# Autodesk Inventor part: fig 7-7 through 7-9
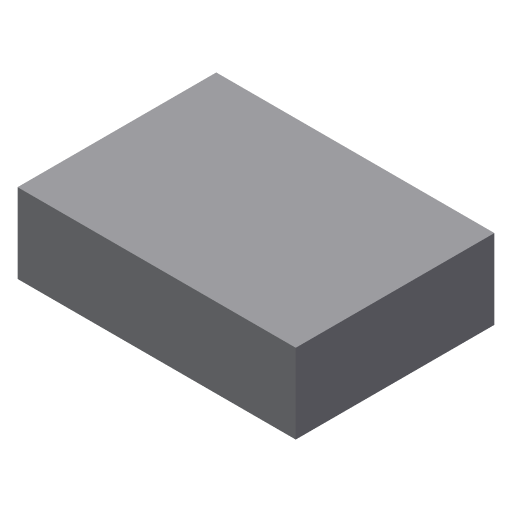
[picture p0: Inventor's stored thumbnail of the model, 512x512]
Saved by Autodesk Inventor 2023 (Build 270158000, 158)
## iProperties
Created: 2009-09
Part Number: fig 7-7 through 7-9
Document SubType Name: Modeling
Designer: Sham
Density: 1 g/cm^3
Material: Generic
Appearance: Default
Author: Sham
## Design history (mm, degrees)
sketch "Sketch1"
  geometry: L1 (-28, 20)-(0, 20); L2 (0, 20)-(0, 0); L3 (0, 0)-(-28, 0); L4 (-28, 0)-(-28, 20)
  constraints: 8 end point, 2 parallel, 1 horizontal, 1 perpendicular
extrude "Extrusion1" new body sketch "Sketch1" distance "d0" = 8; taper "d1" = 0 deg
body "Solid1"
